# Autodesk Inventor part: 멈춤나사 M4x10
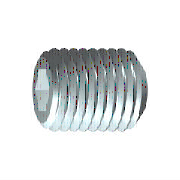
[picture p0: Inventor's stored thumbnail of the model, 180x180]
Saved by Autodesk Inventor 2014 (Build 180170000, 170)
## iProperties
Created: 2012-02
Part Number: 멈춤나사 M4x10
Material: 강철, 연강
Description: 6각 소켓 머리 없는 멈춤 나사
Document SubType Name: Modeling
Standard: KS B 1028
Designer: mduedu
Standards Organization: KS
Language: ko-KR
Size Designation: 납작점M4x10
Categories: <MemberInstance><Categories><Category DisplayName="조임쇠" InternalName="e4da775c-781d-43d5-af7c-5136215cf5a6" Mnemonic="FSTN"><Category DisplayName="볼트" InternalN
Density: 1 g/cm^3
Appearance: Steel
IsCustomPart: 1
Author: mduedu
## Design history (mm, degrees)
sketch "스케치1"
  geometry: L1 (0, 0)-(6.833, 0); L2 (10, 1.155)-(10, 2); L3 (10, 2)-(0, 2); L4 (10, 1.155)-(7.5, 1.155); L5 (7.5, 1.155)-(6.833, 0); L6 (0, -0.4)-(0, 2.4) reference; L7 (0, 2)-(0, 0)
  constraints: 13 end point, 3 parallel, 1 collinear, 1 perpendicular, 1 point on line
  dimensions: "d0" = 2.5 distance of L2.start L4.end (= INTI); "d1" = 60 deg angle of L5 L1; "d2" = 4 diameter of L3 L1 (= NND); "d3" = 2.3094 diameter of L4 L1 (= 1.1547 x SW); "d5" = 10 distance from line of L2 L3.end (= NLG)
revolve "본체" sketch "스케치1" stored, may be unused: angle "d6" = 90 deg
sketch "스케치2"
  geometry: L1 (-0.577, 1)-(0.577, 1); L2 (0.577, 1)-(1.155, 0); L3 (1.155, 0)-(0.577, -1); L4 (0.577, -1)-(-0.577, -1); L5 (-0.577, -1)-(-1.155, 0); L6 (-1.155, 0)-(-0.577, 1); A1 r 1.155 centre (0, 0) between (-0.577, 1) and (0.577, 1) reference; 2 further points
  constraints: 12 end point, 2 point on circle, 1 coincident, 1 horizontal, 11 other
extrude "슬롯" join sketch "스케치2" taper "d9" = 0 deg; stored distance "d21" = 10
workaxis "Work Axis1"
workplane "Work Plane1"
workpoint "Work Point1"
  workaxis "Work Axis2"
body "Solid1"
chamfer "모따기1" distance "d7" = 0.42941 (= -0.5 x GD1 + 0.5 x NND); stored, may be unused: angle "d8" = 45 deg (= FAWI), second distance "d29" = 0.42941 (= -0.5 x GD1 + 0.5 x NND)
feature "스레드" dims "d11" = 10 (= NLG), "d12" = 0
chamfer "모따기2" distance "d13" = 0.42941 (= -0.5 x GD1 + 0.5 x NND); stored, may be unused: angle "d14" = 45 deg (= FAWI), second distance "d30" = 0.42941 (= -0.5 x GD1 + 0.5 x NND)
other parameters: "NND" = 4 [user parameter; used in 5 equation terms], "NLG" = 10 [user parameter; used in 2 equation terms], "INTI" = 2.5 [user parameter; used in 1 equation term], "FAWI" = 45 deg [user parameter; used in 2 equation terms], "SW" = 2 [user parameter; used in 2 equation terms], "GD1" = 3.14117 (= THREADDIA - 1.2269 x PTC) [user parameter; used in 4 equation terms], "d4" = 0, "FAWI1" = 45 deg [user parameter], "d15" = 0, "d31" = 0, "GUL" = 0.42941 (= 0.61345 x PTC) [user parameter], "SPD" = 2.5 [user parameter], "TPU" = 14.28571 (computed from PTC) [user parameter], "TOA" = 30 deg [user parameter], "THREADDIA" = 4 [user parameter; used in 1 equation term], "PTC" = 0.7 [user parameter; used in 4 equation terms], "GAL" = 0.42941 (= 0.61345 x PTC) [user parameter], "E0" = 2.31 (= 1.155 x SW) [user parameter]
